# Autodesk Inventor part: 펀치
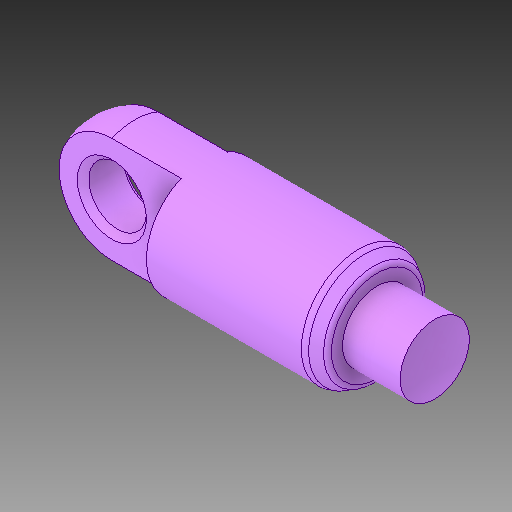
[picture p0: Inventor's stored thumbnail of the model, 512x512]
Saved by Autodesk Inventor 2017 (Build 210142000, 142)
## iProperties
Created: 2024-08
Part Number: 펀치
Material: 일반
Document SubType Name: Modeling
Designer: MRC
Density: 1 g/cm^3
Appearance: 기본값
Author: jhkim
Sending System: Autodesk Inventor 2025
Preprocessor: ST-DEVELOPER v20
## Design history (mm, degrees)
feature "솔리드1"
node "솔리드2"
